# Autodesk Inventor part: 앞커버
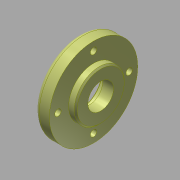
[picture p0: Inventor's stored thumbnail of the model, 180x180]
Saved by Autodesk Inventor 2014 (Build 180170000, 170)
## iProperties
Created: 2015-12
Part Number: 앞커버
Document SubType Name: Modeling
Designer: mdu
Density: 2.71 g/cm^3
Material: 알루미늄 6061
Mass: 70.9292 g
Surface Area: 93.9296 cm^2
Volume: 26.1731 cm^3
Appearance: 알루미늄 - 평지
Author: mdu
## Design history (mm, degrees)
sketch "스케치1"
  geometry: L1 (-7.5, 0)-(7.5, 0); L2 (-7.5, 0)-(-7.5, 31); L3 (-7.5, 31)-(2.5, 31); L4 (2.5, 31)-(2.5, 17.5); L5 (2.5, 17.5)-(7.5, 17.5); L6 (7.5, 17.5)-(7.5, 0); 2 further points
  constraints: 12 end point, 3 perpendicular, 1 coincident, 1 horizontal, 1 midpoint, 1 parallel
  dimensions: "d0" = 15 distance of L1.start L1.end; "d1" = 62 diameter of L3 L1; "d2" = 35 diameter of L5 L1; "d5" = 10 distance of L2.end L3.end
revolve "회전1" sketch "스케치1" stored, may be unused: angle "d6" = 90 deg
sketch "스케치2" dims "d42" = 50
  geometry: 3 further points
  constraints: 2 vertical alignment, 1 coincident, 2 other
hole "구멍1" sketch "스케치2" at (0, 25) diameter "d8" = 4.5; stored, may be unused: countersink angle "d12" = 90 deg, drill point angle "d14" = 118 deg; dims "d9" = 6, "d10" = 8, "d11" = 4.4, "d13" = 8
hole "구멍2" diameter "d20" = 18; stored, may be unused: countersink angle "d24" = 90 deg, drill point angle "d26" = 0 deg; dims "d18" = 10, "d19" = 10, "d21" = 6, "d22" = 8, "d23" = 4.4, "d25" = 8
hole "구멍3" diameter "d34" = 30; stored, may be unused: countersink angle "d38" = 90 deg, drill point angle "d40" = 0 deg; dims "d32" = 10, "d33" = 10, "d35" = 6, "d36" = 4, "d37" = 2, "d39" = 7.3
fillet "모깎기1" dims "d27" = 3, "d41" = 0.3
chamfer "모따기1" distance "d29" = 1; stored, may be unused: second distance "d30" = 2, angle "d31" = 45 deg
node "솔리드1"
pattern_circular "원형 패턴1" dims angle "d16" = 360 deg
